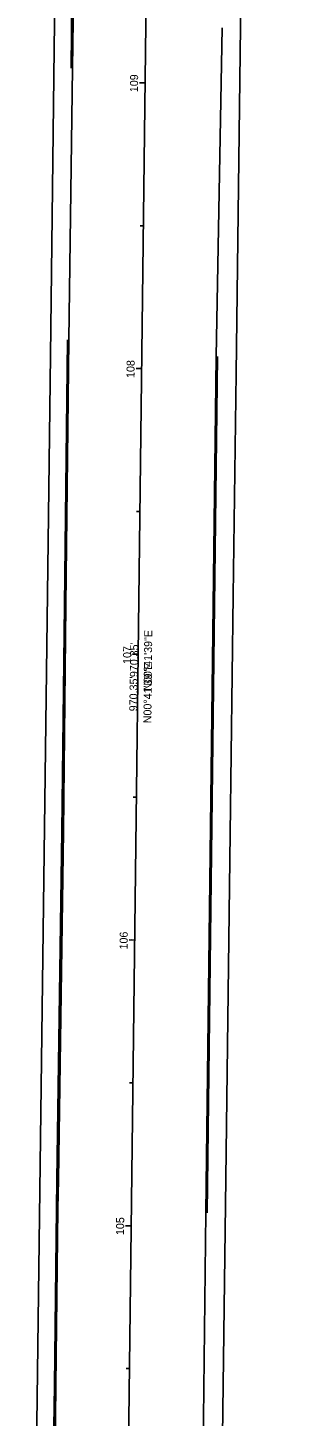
# Model space of a CAD drawing. Extents: x 1652464 to 1652601, y 605963 to 608618.
# Drawn here: x 1652507.3 to 1652601.5, y 606449.1 to 606935 of the extents above; entities that cross this region are included whole.
import ezdxf

# ---------------------------------------------------------------- set-up
doc = ezdxf.new("R2010")
doc.units = 0
for name, color, linetype in [('BD_X_Building', 7, 'Continuous'), ('BR_X_SV_Abut', 7, 'Continuous'), ('DR_X_Erosion_Control', 7, 'Continuous'), ('GE_X_Cells', 7, 'Continuous'), ('PV_X_Curb', 7, 'Continuous'), ('PV_X_Steps', 7, 'Continuous'), ('PV_X_Walk', 7, 'Continuous'), ('SV_P_Mon_Cells_Set', 7, 'Continuous'), ('SV_X_Control_Cells_Found', 7, 'Continuous'), ('SV_X_Mon_Cells_Found', 7, 'Continuous'), ('UT_X_Water_Cells', 7, 'Continuous'), ('VG_X_Cells', 7, 'Continuous'), ('VG_X_Shrub_Line_Lt', 7, 'Continuous')]:
    doc.layers.add(name, color=color, linetype=linetype)

msp = doc.modelspace()

# ---------------------------------------------------------------- linework, layer by layer
at = {"layer": 'BD_X_Building'}
msp.add_lwpolyline([(1652507.27, 606201.32), (1652514.36, 606755.06), (1652515.19, 606820.32), (1652516.55, 606927.44), (1652537.47, 608602.59)], dxfattribs=at)
at = {"layer": 'GE_X_Cells'}
for p, q in [((1652522.93, 606920.85), (1652525.17, 607110.06)), ((1652573.16, 606819.96), (1652575.19, 606934.98)), ((1652573.16, 606819.96), (1652575.19, 606934.98)), ((1652573.16, 606819.96), (1652575.19, 606934.98)), ((1652573.16, 606819.96), (1652575.19, 606934.98)), ((1652573.16, 606819.96), (1652575.19, 606934.98)), ((1652573.16, 606819.96), (1652575.19, 606934.98)), ((1652521.66, 606825.75), (1652522.93, 606920.85)), ((1652520.61, 606732.88), (1652521.66, 606825.75)), ((1652569.53, 606520.3), (1652573.16, 606819.96)), ((1652569.53, 606520.3), (1652573.16, 606819.96)), ((1652569.53, 606520.3), (1652573.16, 606819.96)), ((1652569.53, 606520.3), (1652573.16, 606819.96)), ((1652569.53, 606520.3), (1652573.16, 606819.96)), ((1652569.53, 606520.3), (1652573.16, 606819.96)), ((1652519.7, 606653.67), (1652520.61, 606732.88)), ((1652517.96, 606531.8), (1652519.7, 606653.67)), ((1652517.83, 606521.72), (1652517.96, 606531.8)), ((1652517.12, 606459.77), (1652517.83, 606521.72)), ((1652568.47, 606432.68), (1652569.53, 606520.3)), ((1652568.47, 606432.68), (1652569.53, 606520.3)), ((1652568.47, 606432.68), (1652569.53, 606520.3)), ((1652568.47, 606432.68), (1652569.53, 606520.3)), ((1652568.47, 606432.68), (1652569.53, 606520.3)), ((1652568.47, 606432.68), (1652569.53, 606520.3)), ((1652514.05, 606240.46), (1652517.12, 606459.77))]:
    msp.add_line(p, q, dxfattribs=at)
at = {"layer": 'PV_X_Curb'}
for p, q in [((1652540.01, 606229.06), (1652551.76, 607199.34)), ((1652573.66, 606819.96), (1652570.03, 606520.29))]:
    msp.add_line(p, q, dxfattribs=at)
at = {"layer": 'PV_X_Steps'}
msp.add_lwpolyline([(1652570.42, 606048.23), (1652570.59, 606069.16), (1652572.96, 606254.92), (1652575.24, 606433.07), (1652576.4, 606523.06), (1652578.06, 606652.96), (1652579.12, 606736.34), (1652580.12, 606814.04), (1652581.65, 606935.48), (1652585.26, 607224.58), (1652586.28, 607305.92), (1652588.75, 607503.82), (1652591.34, 607710.88), (1652594.35, 607951.77), (1652594.72, 607981.92), (1652597.89, 608234.94), (1652601.47, 608521.97)], dxfattribs=at)
at = {"layer": 'PV_X_Walk'}
for p, q in [((1652522.43, 606920.86), (1652524.67, 607110.06)), ((1652520.11, 606732.88), (1652521.16, 606825.75)), ((1652513.55, 606240.47), (1652516.62, 606459.78))]:
    msp.add_line(p, q, dxfattribs=at)
msp.add_lwpolyline([(1652516.62, 606459.78), (1652517.33, 606521.73), (1652517.46, 606531.8), (1652519.2, 606653.68), (1652520.11, 606732.88)], dxfattribs=at)
at = {"layer": 'SV_X_Control_Cells_Found'}
msp.add_line((1652540.01, 606229.06), (1652551.76, 607199.34), dxfattribs=at)
msp.add_line((1652540.01, 606229.06), (1652551.76, 607199.34), dxfattribs=at)
at = {"layer": 'SV_X_Mon_Cells_Found'}
msp.add_circle((1652545.88, 606714.2), 0.05, dxfattribs=at)
msp.add_circle((1652545.88, 606714.2), 0.05, dxfattribs=at)
at = {"layer": 'VG_X_Cells'}
for p, q in [((1652548.32, 606915.71), (1652546.32, 606915.73)), ((1652547.72, 606865.71), (1652546.52, 606865.72)), ((1652547.11, 606815.71), (1652545.11, 606815.74)), ((1652546.51, 606765.72), (1652545.31, 606765.73)), ((1652545.9, 606715.72), (1652543.9, 606715.75)), ((1652545.3, 606665.72), (1652544.1, 606665.74)), ((1652544.69, 606615.73), (1652542.69, 606615.75)), ((1652544.08, 606565.73), (1652542.88, 606565.75)), ((1652543.48, 606515.74), (1652541.48, 606515.76)), ((1652542.87, 606465.74), (1652541.67, 606465.75))]:
    msp.add_line(p, q, dxfattribs=at)
at = {"layer": 'VG_X_Shrub_Line_Lt'}
for p, q in [((1652548.32, 606915.71), (1652547.12, 606915.72)), ((1652547.11, 606815.71), (1652545.91, 606815.73)), ((1652545.9, 606715.72), (1652544.7, 606715.74)), ((1652544.69, 606615.73), (1652543.49, 606615.74)), ((1652543.48, 606515.74), (1652541.48, 606515.76))]:
    msp.add_line(p, q, dxfattribs=at)

# ---------------------------------------------------------------- texts
at = {"layer": 'BR_X_SV_Abut'}
msp.add_text('N00°41\'39"E', height=2.8, rotation=89.3059, dxfattribs=at).set_placement((1652550.55, 606702.96))
at = {"layer": 'DR_X_Erosion_Control'}
msp.add_text("970.35'", height=2.8, rotation=89.3059, dxfattribs=at).set_placement((1652545.76, 606707.71))
at = {"layer": 'SV_P_Mon_Cells_Set'}
msp.add_text('N00°41\'39"E', height=2.8, rotation=89.3059, dxfattribs=at).set_placement((1652550.48, 606691.57))
at = {"layer": 'UT_X_Water_Cells'}
msp.add_text("970.35'", height=2.8, rotation=89.3059, dxfattribs=at).set_placement((1652545.56, 606695.76))
at = {"layer": 'VG_X_Cells'}
for s, p in [('109', (1652545.78, 606912.42)), ('108', (1652544.57, 606812.41)), ('107', (1652543.36, 606712.33)), ('106', (1652542.15, 606612.4)), ('105', (1652540.94, 606512.46))]:
    msp.add_text(s, height=2.8, rotation=89.3059, dxfattribs=at).set_placement(p)
at = {"layer": 'VG_X_Shrub_Line_Lt'}
msp.add_text('105', height=2.8, rotation=89.3059, dxfattribs=at).set_placement((1652540.9, 606512.46))

doc.saveas('drawing.dxf')
